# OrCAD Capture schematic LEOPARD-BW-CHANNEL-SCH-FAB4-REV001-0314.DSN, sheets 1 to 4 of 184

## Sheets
1 100_miniSAS CONNECTORS_SATA: size A2; title: MiniSAS CONNECTORS_SATA; rev: EVT; company: Wiwynn Corporation; note: LEOPARD BDW MAIN BOARD; note: 8F, 90, Sec.1, Xintai 5th Rd., Xizhi Dist.,; note: New Taipei, Taiwan
2 177_P3V3_STBY_TPS53318: size A3; title: P3V3_STBY_TPS53318; rev: PVT; note: 8F, No.90, Xintai 5th Rd., Xizhi Dist,
3 176_P3V3_TPS53319: size C; title: P3V3_TPS53319
4 175_P5V_STBY_TPS53319: size A3; title: P5V_STBY_TPS53319

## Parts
sheet 100_miniSAS CONNECTORS_SATA
C719  SCD01U16V2KX-3GP  [C402H22]
C723  SCD01U16V2KX-3GP  [C402H22]
C726  SCD01U16V2KX-3GP  [C402H22]
C728  SCD01U16V2KX-3GP  [C402H22]
C729  SCD01U16V2KX-3GP  [C402H22]
C730  SCD01U16V2KX-3GP  [C402H22]
C731  SCD01U16V2KX-3GP  [C402H22]
C733  SCD01U16V2KX-3GP  [C402H22]
C1019  SCD01U16V2KX-3GP  [C402H22]
C1020  SCD01U16V2KX-3GP  [C402H22]
C1021  SCD01U16V2KX-3GP  [C402H22]
C1022  SCD01U16V2KX-3GP  [C402H22]
C1023  SCD01U16V2KX-3GP  [C402H22]
C1024  SCD01U16V2KX-3GP  [C402H22]
C1025  SCD01U16V2KX-3GP  [C402H22]
C1026  SCD01U16V2KX-3GP  [C402H22]
C1027  SCD01U16V2KX-3GP  [C402H22]
C1028  SCD01U16V2KX-3GP  [C402H22]
C1029  SCD01U16V2KX-3GP  [C402H22]
C1030  SCD01U16V2KX-3GP  [C402H22]
C1031  SCD01U16V2KX-3GP  [C402H22]
C1032  SCD01U16V2KX-3GP  [C402H22]
C1033  SCD01U16V2KX-3GP  [C402H22]
C1034  SCD01U16V2KX-3GP  [C402H22]
C1035  SCD01U16V2KX-3GP  [C402H22]
C1036  SCD01U16V2KX-3GP  [C402H22]
C1037  SCD01U16V2KX-3GP  [C402H22]
C1038  SCD01U16V2KX-3GP  [C402H22]
C1039  SCD01U16V2KX-3GP  [C402H22]
C1040  SCD01U16V2KX-3GP  [C402H22]
C1041  SCD01U16V2KX-3GP  [C402H22]
C1042  SCD01U16V2KX-3GP  [C402H22]
MISAS1  AMP-CONN36-GP  [75784-0121]
MISAS2  AMP-CONN36-GP  [75784-0121]
R206  49D9R2F-GP  [R402H16]
R291  2KR2F-3-GP  [R402H16]
R293  2KR2F-3-GP  [R402H16]
R294  2KR2F-3-GP  [R402H16]
R295  2KR2F-3-GP  [R402H16]
R832  2KR2F-3-GP  [R402H16]
R835  2KR2F-3-GP  [R402H16]
R839  2KR2F-3-GP  [R402H16]
R840  2KR2F-3-GP  [R402H16]
R901  49D9R2F-GP  [R402H16]
R905  49D9R2F-GP  [R402H16]
R1262  49D9R2F-GP  [R402H16]
R1264  49D9R2F-GP  [R402H16]
R1265  49D9R2F-GP  [R402H16]
R1819  1KR2J-1-GP  [R402H16]
R1820  1KR2J-1-GP  [R402H16]
sheet 175_P5V_STBY_TPS53319
PC881  SC22U6D3V5MX-5-GP  [C805H56]
PC882  SC22U6D3V5MX-5-GP  [C805H56]
PC883  SC22U6D3V5MX-5-GP  [C805H56]
PC884  SC22U6D3V5MX-5-GP  [C805H56]
PC885  SC22U6D3V5MX-5-GP  [C805H56]
PC886  SC22U6D3V5MX-5-GP  [C805H56]
PC913  SCD1U16V2KX-3GP  [C402H22]
PC914  SC10U16V5KX-1-GP  [C805H54]
PC920  SC1U16V3KX-5GP  [C603H36]
PC921  SCD1U50V3KX-GP  [C603H36]
PC931  SC1KP50V2KX-1GP  [C402H22]
PC932  SCD1U16V3KX-3GP  [C603H36]
PC933  SC2K2P50V3KX-GP  [C603]
PC934  SC10U16V5KX-1-GP  [C805H54]
PC935  SCD1U50V3KX-GP  [C603H36]
PC936  SC22U6D3V5MX-5-GP  [C805H56]
PC937  SC10U16V5KX-1-GP  [C805H54]
PC938  SC10U16V5KX-1-GP  [C805H54]
PC939  SC10U16V5KX-1-GP  [C805H54]
PC940  SC4D7U25V5KX-1-GP  [C805H58]
PC1064  SC1U10V2KX-4-GP  [C402H22]
PD12  PTZ5D6B-GP  [D502715AKH87]
PG67  COPPER-CLOSE-GP-U  [CON2C-U]
PG68  GAP-CLOSE-PWR-4-GP  [GAP-CLOSE-PWR-4]
PL51  COIL-1UH-50-GP  [L7467-1432-1H119]
PL52  BLM21PG220SN1DGP  [L20125H42]
PR520  10KR2F-2-GP  [R402H16]
PR521  15KR2F-GP  [R402H16]
PR522  10KR2F-2-GP  [R402H16]
PR545  0R2J-2-GP  [R402H16]
PR628  2D7R3-GP  [R603H22]
PR631  2D2R3-1-U-GP  [R603H22]
PR634  10R3F-GP  [R603H22]
PR636  124KR2F-GP  [R402H16]
PR639  619KR2F-GP  [R402H16]
PR641  866KR2F-GP  [R402H16]
PR647  3D01R5F-GP  [R805H24]
PR648  1KR3F-GP  [R603H22]
PR650  71K5R3F-1-GP  [R603H22]
PR651  200KR2F-L-GP  [R402H16]
PR652  100KR2F-L1-GP  [R402H16]
PR653  10KR2F-2-GP  [R402H16]
PR816  0R2J-2-GP  [R402H16]
PR1910  2K2R2F-GP  [R402H16]
PU52  TPS53319DQPR-GP  [QFN22G6050-G6133H60]
sheet 176_P3V3_TPS53319
PC485  SC470P50V2KX-3GP  [C402H22]
PC790  SC22U6D3V5MX-5-GP  [C805H56]
PC792  SC22U6D3V5MX-5-GP  [C805H56]
PC793  SC22U6D3V5MX-5-GP  [C805H56]
PC794  SC22U6D3V5MX-5-GP  [C805H56]
PC795  SC22U6D3V5MX-5-GP  [C805H56]
PC836  SC22U6D3V5MX-5-GP  [C805H56]
PC904  SC10U16V5KX-1-GP  [C805H54]
PC905  SC10U16V5KX-1-GP  [C805H54]
PC906  SC10U16V5KX-1-GP  [C805H54]
PC907  SCD1U16V2KX-3GP  [C402H22]
PC908  SCD1U16V3KX-3GP  [C603H36]
PC909  SC22U6D3V5MX-5-GP  [C805H56]
PC911  SC10U16V5KX-1-GP  [C805H54]
PC917  SCD1U50V3KX-GP  [C603H36]
PC918  SC2K2P50V3KX-GP  [C603]
PC919  SCD1U50V3KX-GP  [C603H36]
PC941  SC4D7U25V5KX-1-GP  [C805H58]
PC942  SC1U16V3KX-5GP  [C603H36]
PC1055  SC1U10V2KX-4-GP  [C402H22]
PD11  PTZ5D6B-GP  [D502715AKH87]
PG64  COPPER-CLOSE-GP-U  [CON2C-U]
PL49  IND-1UH-188-GP  [L7166-1830-UH197]
PL50  BLM21PG220SN1DGP  [L20125H42]
PR2  147KR2F-L-GP  [R402H16]
PR3  309KR2F-GP  [R402H16]
PR4  309KR2F-GP  [R402H16]
PR347  20KR2F-L-GP  [R402H16]
PR441  10KR2F-2-GP  [R402H16]
PR481  2D7R3-GP  [R603H22]
PR540  10KR2F-2-GP  [R402H16]
PR541  10KR2F-2-GP  [R402H16]
PR543  0R2J-2-GP  [R402H16]
PR633  10R3F-GP  [R603H22]
PR635  44K2R2F-1-GP  [R402H16]
PR638  10KR2F-2-GP  [R402H16]
PR640  2KR2F-3-GP  [R402H16]
PR642  3D01R5F-GP  [R805H24]
PR649  2D2R3-1-U-GP  [R603H22]
PR817  0R2J-2-GP  [R402H16]
PR2171  39K2R2F-L-GP  [R402H16]
PR2172  39K2R2F-L-GP  [R402H16]
PU54  TPS53319DQPR-GP  [QFN22G6050-G6133H60]
sheet 177_P3V3_STBY_TPS53318
PC376  SC470P50V2KX-3GP  [C402H22]
PC386  SC1U10V2KX-4-GP  [C402H22]
PC392  SCD1U25V3KX-GP  [C603H36]
PC395  SCD1U50V3KX-GP  [C603H36]
PC488  SC2K2P50V3KX-GP  [C603]
PC489  SC4D7U25V5KX-1-GP  [C805H58]
PC808  SC22U6D3V5MX-5-GP  [C805H56]
PC835  SC10U16V5KX-1-GP  [C805H54]
PC851  SC10U16V5KX-1-GP  [C805H54]
PC852  SC10U16V5KX-1-GP  [C805H54]
PC1036  SC1U10V2KX-4-GP  [C402H22]
PG81  COPPER-CLOSE-GP-U  [CON2C-U]
PL19  BLM21PG220SN1DGP  [L20125H42]
PL42  IND-2D2UH-179-GP  [L7066-1830-UH119]
PR199  10R3F-GP  [R603H22]
PR200  0R5J-2  [R805H24]
PR201  2KR2F-3-GP  [R402H16]
PR202  100KR2F-L1-GP  [R402H16]
PR203  10KR2F-2-GP  [R402H16]
PR204  100KR2F-L1-GP  [R402H16]
PR207  475KR2F-GP  [R402H16]
PR209  3D01R5F-GP  [R805H24]
PR210  44K2R2F-1-GP  [R402H16]
PR211  0R2J-2-GP  [R402H16]
PR213  309KR2F-GP  [R402H16]
PR214  2D2R3-1-U-GP  [R603H22]
PR654  10KR2F-2-GP  [R402H16]
PTC19  ST150U6D3VBM-6-GP  [CT3528H83]
PU44  TPS53318DQPR-GP  [DFN22G6050-G6133H60]

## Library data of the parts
C719 C723 C726 C728-C731 C733 C1019-C1042 = SCD01U16V2KX-3GP: CHIP CAP0.01U16V K0402 X7R(ROH; Belong: POP; Category: PCH SAS; POP?: NOPOP; Part Number: 78.10321.2FL; Part Type: SMD-BCG
MISAS1 MISAS2 = AMP-CONN36-GP: CONN CTR SMD 36P G40MV36U11AEU ,LCP; GREENDFACTOR: R2_SA;; POP?: NOPOP; Part Number: 20.F1014.036; Part Type: CONN-G1; SPEC: http://wpqssvr.wistron.com.tw:7001/wpqs/servlet/COM.qpart.Attachment?PartNumber=20.F1014.036
R206 R901 R905 R1262 R1264 R1265 = 49D9R2F-GP: CHIP RES 49.9 F 1/16W 0402; GREENDFACTOR: R2_SA;HF_SA;G_SA;; POP?: NOPOP; Part Number: 64.49R95.6DL; Part Type: RCL_GP; SPEC: http://wpqssvr.wistron.com.tw:7001/wpqs/servlet/COM.qpart.Attachment?PartNumber=64.49R95.6DL
PR201 R291 R293-R295 R832 R835 R839 R840 = 2KR2F-3-GP: CHIP RES 2K F 1/16W 0402; Category: internal conn; DESCRIPTIO: CHIP RES 2K F 1/16W 0402; GREENDFACTOR: R2_SA;HF_SA;G_SA;; Package Type: SMD-RG; Part Number: 64.20015.6DL; Part Type: SMD-RG; SPEC: http://wpqssvr.wistron.com.tw:7001/wpqs/servlet/COM.qpart.Attachment?PartNumber=64.20015.6DL; VENDORPARTNUMBER: RM04FTN2001 / RTT022001FTH / RR0510S-202-FN / RC0402FR-072KL/WR04X2001FTL
R1819 R1820 = 1KR2J-1-GP: CHIP RES 1K J 1/16W 0402; GREENDFACTOR: R2_SA;HF_SA;G_SA;; POP?: NOPOP; Part Number: 63.10234.1DL; Part Type: SMD-RG; SPEC: http://wpqssvr.wistron.com.tw:7001/wpqs/servlet/COM.qpart.Attachment?PartNumber=63.10234.1DL
PC790 PC792-PC795 PC808 PC836 PC881-PC886 PC909 PC936 = SC22U6D3V5MX-5-GP: CHIP CAP C 22U 6.3V M0805 X6S; GREENDFACTOR: R2_SA;HF_SA;G_SA;; Package Type: SMD-BCG2; Part Number: 78.22610.81L; SPEC: http://wpqssvr.wistron.com.tw:7001/wpqs/servlet/COM.qpart.Attachment?PartNumber=78.22610.81L
PC907 PC913 = SCD1U16V2KX-3GP: CHIP CAP C 0.1U 16V K0402 X7R; GREENDFACTOR: R2_SA;HF_SA;G_SA;; MAIN_SOURCE: M; Package Type: SMD-BCG; Part Number: 78.10421.2FL; SPEC: http://wpqssvr.wistron.com.tw:7001/wpqs/servlet/COM.qpart.Attachment?PartNumber=78.10421.2FL
PC835 PC851 PC852 PC904-PC906 PC911 PC914 PC934 PC937-PC939 = SC10U16V5KX-1-GP: CHIP CAP C 10U 16V K0805 X6S; GREENDFACTOR: R2_SA;; Package Type: SMD-BCG5; Part Number: 78.10621.81L; SPEC: http://wpqssvr.wistron.com.tw:7001/wpqs/servlet/COM.qpart.Attachment?PartNumber=78.10621.81L
PC920 PC942 = SC1U16V3KX-5GP: CHIP CAP C 1U 16V K0603 X7R; GREENDFACTOR: R2_SA;HF_SA;G_SA;; Level: SMD; MAIN_SOURCE: M; Package Type: SMD-BCG3; Part Number: 78.10521.2BL; SPEC: http://wpqssvr.wistron.com.tw:7001/wpqs/servlet/COM.qpart.Attachment?PartNumber=78.10521.2BL; Status: POP
PC395 PC917 PC919 PC921 PC935 = SCD1U50V3KX-GP: CHIP CAP C 0.1U 50V K0603 X7R; GREENDFACTOR: R2_SA;HF_SA;G_SA;; Level: SMD; MAIN_SOURCE: M; Package Type: RCL_GP; Part Number: 78.10424.2BL; Part Type: RCL_GP; SPEC: http://wpqssvr.wistron.com.tw:7001/wpqs/servlet/COM.qpart.Attachment?PartNumber=78.10424.2BL; Status: POP
PC931 = SC1KP50V2KX-1GP: CHIP CAP 1000P50V K0402 X7R(RO; GREENDFACTOR: R2_SA;HF_SA;G_SA;; Level: SMD; MAIN_SOURCE: M; Package Type: SMD-BCG; Part Number: 78.10224.2FL; Part Type: SMD-BCG; SPEC: http://wpqssvr.wistron.com.tw:7001/wpqs/servlet/COM.qpart.Attachment?PartNumber=78.10224.2FL; Status: POP
PC908 PC932 = SCD1U16V3KX-3GP: CHIP CAP 0.1U16V K0603 X7R(ROH; GREENDFACTOR: R2_SA;R_SA;HF_SA;G_SA;; Module: VR_SYSTEM_P1V8; Package Type: SMD-BCG; Part Number: 78.10421.2BL; SPEC: http://wpqssvr.wistron.com.tw:7001/wpqs/servlet/COM.qpart.Attachment?PartNumber=78.10421.2BL; Size: 0603; Type: X7R
PC918 PC933 = SC2K2P50V3KX-GP: CHIP CAP C 2200P 50V K0603 X7R; GREENDFACTOR: R2_SA;HF_SA;G_SA;; Level: SMD; POP?: NOPOP; Package Type: SMD-BCG6; Part Number: 78.22224.2BL; Part Type: SMD-BCG6; SPEC: http://wpqssvr.wistron.com.tw:7001/wpqs/servlet/COM.qpart.Attachment?PartNumber=78.22224.2BL
PC489 PC940 PC941 = SC4D7U25V5KX-1-GP: CHIP CAP C 4.7U 25V K0805 X7R; GREENDFACTOR: R2_SA;HF_SA;G_SA;; Package Type: SMD-BCG4; Part Number: 078.47522.0211; SPEC: http://wpqssvr.wistron.com.tw:7001/wpqs/servlet/COM.qpart.Attachment?PartNumber=078.47522.0211
PC386 PC1064 = SC1U10V2KX-4-GP: CHIP CAP C 1U 10V K 0402 X6S; GREENDFACTOR: R2_SA;HF_SA;; Package Type: SMD-BCG6; Part Number: 78.10523.8FL; SPEC: http://wpqssvr.wistron.com.tw:7001/wpqs/servlet/COM.qpart.Attachment?PartNumber=78.10523.8FL
PD11 PD12 = PTZ5D6B-GP: DIODE ZEN PTZ5.6B 5.6V PMDS; GREENDFACTOR: R2_SA;; Package Type: DISCRET-G5; Part Number: 83.5R603.H3H; SPEC: http://wpqssvr.wistron.com.tw:7001/wpqs/servlet/COM.qpart.Attachment?PartNumber=83.5R603.H3H
PG64 PG67 PG81 = COPPER-CLOSE-GP-U: COPPER CLOSE; GREENDFACTOR: Regular;; Level: SMD; Package Type: DISCRET-G9; Part Number: ZZ.CON2C.XXX; Part Type: DISCRET-G9; SPEC: http://wpqssvr.wistron.com.tw:7001/wpqs/servlet/COM.qpart.Attachment?PartNumber=ZZ.CON2C.XXX
PG68 = GAP-CLOSE-PWR-4-GP: PAD FOR COPPER-CLOSE; GREENDFACTOR: R2_C;; Package Type: DISCRET-G7; Part Number: ZZ.C0N2C.011; SPEC: http://wpqssvr.wistron.com.tw:7001/wpqs/servlet/COM.qpart.Attachment?PartNumber=ZZ.C0N2C.011
PL51 = COIL-1UH-50-GP: CHIP CHOKE 1.0UH MPLCG0630L1R0; GREENDFACTOR: R2_SA;HF_SA;; Package Type: DISCRET-G4; Part Number: 68.1R010.20C; SPEC: http://wpqssvr.wistron.com.tw:7001/wpqs/servlet/COM.qpart.Attachment?PartNumber=68.1R010.20C
PL50 PL52 = BLM21PG220SN1DGP: CHIP BEAD BLM21PG220SN1D (LF); GREENDFACTOR: R2_SA;HF_SA;; Level: SMD; Package Type: DISCRET-G; Part Number: 68.00084.831; Part Type: DISCRET-G; SPEC: http://wpqssvr.wistron.com.tw:7001/wpqs/servlet/COM.qpart.Attachment?PartNumber=68.00084.831
PR520 PR522 = 10KR2F-2-GP: CHIP RES 10K F 1/16W 0402; GREENDFACTOR: R2_SA;HF_SA;G_SA;; Level: SMD; Package Type: SMD-RG; Part Number: 64.10025.6DL; SPEC: http://wpqssvr.wistron.com.tw:7001/wpqs/servlet/COM.qpart.Attachment?PartNumber=64.10025.6DL; Status: POP
PR521 = 15KR2F-GP: CHIP RES 15K F 1/16W 0402; GREENDFACTOR: R2_SA;HF_SA;G_SA;; Package Type: RCL_GP; Part Number: 64.15025.6DL; SPEC: http://wpqssvr.wistron.com.tw:7001/wpqs/servlet/COM.qpart.Attachment?PartNumber=64.15025.6DL
PR545 = 0R2J-2-GP: CHIP RES 0 J 1/16W 0402; Belong: POP; Category: Reset/PWRGD Logic; GREENDFACTOR: R2_SA;HF_SA;G_SA;; POP?: NOPOP; Part Number: 63.R0034.1DL; Part Type: SMD-RG; SPEC: http://wpqssvr.wistron.com.tw:7001/wpqs/servlet/COM.qpart.Attachment?PartNumber=63.R0034.1DL
PR481 PR628 = 2D7R3-GP: CHIP RES 2.7 J 1/10W 0603; GREENDFACTOR: R2_SA;HF_SA;G_SA;; Package Type: RCL_GP; Part Number: 63.2R734.15L; SPEC: http://wpqssvr.wistron.com.tw:7001/wpqs/servlet/COM.qpart.Attachment?PartNumber=63.2R734.15L
PR214 PR631 PR649 = 2D2R3-1-U-GP: CHIP RES 2.2 F 1/10W 0603(ROHS; GREENDFACTOR: R2_SA;HF_SA;G_SA;; Package Type: RCL_GP; Part Number: 64.2R205.55L; SPEC: http://wpqssvr.wistron.com.tw:7001/wpqs/servlet/COM.qpart.Attachment?PartNumber=64.2R205.55L
PR199 PR633 PR634 = 10R3F-GP: CHIP RES 10 F 1/10W 0603; GREENDFACTOR: R2_SA;HF_SA;G_SA;; Level: SMD; Package Type: RCL_GP; Part Number: 64.10R05.55L; Part Type: RCL_GP; SPEC: http://wpqssvr.wistron.com.tw:7001/wpqs/servlet/COM.qpart.Attachment?PartNumber=64.10R05.55L; Status: POP
PR636 = 124KR2F-GP: CHIP RES 124K F 1/16W 0402; GREENDFACTOR: R2_SA;HF_SA;G_SA;; Package Type: RCL_GP; Part Number: 64.12435.6DL; SPEC: http://wpqssvr.wistron.com.tw:7001/wpqs/servlet/COM.qpart.Attachment?PartNumber=64.12435.6DL
PR639 = 619KR2F-GP: CHIP RES 619K F 1/16W 0402; GREENDFACTOR: R2_SA;HF_SA;G_SA;; Level: SMD; POP?: NOPOP; Package Type: SMD-RG3; Part Number: 64.61935.6DL; Part Type: SMD-RG3; SPEC: http://wpqssvr.wistron.com.tw:7001/wpqs/servlet/COM.qpart.Attachment?PartNumber=64.61935.6DL
PR641 = 866KR2F-GP: CHP RES 866K F 1/16W 0402; GREENDFACTOR: R2_SA;HF_SA;G_SA;; Level: SMD; Package Type: SMD-RG4; Part Number: 64.86635.6DL; Part Type: SMD-RG4; SPEC: http://wpqssvr.wistron.com.tw:7001/wpqs/servlet/COM.qpart.Attachment?PartNumber=64.86635.6DL; Status: POP
PR642 PR647 = 3D01R5F-GP: CHIP RES 3.01 F 1/8W 0805; GREENDFACTOR: R2_SA;HF_SA;G_SA;; Level: SMD; POP?: NOPOP; Package Type: SMD-RG5; Part Number: 64.3R015.16L; Part Type: SMD-RG5; SPEC: http://wpqssvr.wistron.com.tw:7001/wpqs/servlet/COM.qpart.Attachment?PartNumber=64.3R015.16L
PR648 = 1KR3F-GP: CHIP RES 1K F 1/10W 0603(ROHS); GREENDFACTOR: R2_SA;HF_SA;G_SA;; Part Number: 64.10015.55L; Part Type: RCL_GP; SPEC: http://wpqssvr.wistron.com.tw:7001/wpqs/servlet/COM.qpart.Attachment?PartNumber=64.10015.55L
PR650 = 71K5R3F-1-GP: CHIP RES 71.5K F 1/10W 0603; GREENDFACTOR: R2_SA;HF_SA;G_SA;; Part Number: 64.71525.55L; Part Type: SMD-RG; SPEC: http://wpqssvr.wistron.com.tw:7001/wpqs/servlet/COM.qpart.Attachment?PartNumber=64.71525.55L
PR651 = 200KR2F-L-GP: CHIP RES 200K F 1/16W 0402; GREENDFACTOR: R2_SA;HF_SA;G_SA;; Package Type: SMD-RG; Part Number: 64.20035.6DL; SPEC: http://wpqssvr.wistron.com.tw:7001/wpqs/servlet/COM.qpart.Attachment?PartNumber=64.20035.6DL
PR652 = 100KR2F-L1-GP: CHIP RES 100K F 1/16W 0402; GREENDFACTOR: R2_SA;HF_SA;G_SA;; Level: SMD; POP?: NOPOP; Package Type: SMD-RG; Part Number: 64.10035.6DL; Part Type: SMD-RG; SPEC: http://wpqssvr.wistron.com.tw:7001/wpqs/servlet/COM.qpart.Attachment?PartNumber=64.10035.6DL
PR441 PR541 PR638 PR653 PR654 = 10KR2F-2-GP: CHIP RES 10K F 1/16W 0402; GREENDFACTOR: R2_SA;HF_SA;G_SA;; Level: SMD; Package Type: SMD-RG; Part Number: 64.10025.6DL; Part Type: SMD-RG; SPEC: http://wpqssvr.wistron.com.tw:7001/wpqs/servlet/COM.qpart.Attachment?PartNumber=64.10025.6DL
PR211 PR816 PR817 = 0R2J-2-GP: CHIP RES 0 J 1/16W 0402; GREENDFACTOR: R2_SA;HF_SA;G_SA;; Level: SMD; Package Type: SMD-RG; Part Number: 63.R0034.1DL; Part Type: SMD-RG; ROOM: VR_CHIPSET; SPEC: http://wpqssvr.wistron.com.tw:7001/wpqs/servlet/COM.qpart.Attachment?PartNumber=63.R0034.1DL; Status: POP
PR1910 = 2K2R2F-GP: CHIP RES 2.2K F 1/16W 0402; GREENDFACTOR: R2_SA;HF_SA;G_SA;; Package Type: RCL_GP; Part Number: 64.22015.6DL; SPEC: http://wpqssvr.wistron.com.tw:7001/wpqs/servlet/COM.qpart.Attachment?PartNumber=64.22015.6DL
PU52 PU54 = TPS53319DQPR-GP: IC PWR CTRL TPS53319DQPR QFN 22P; GREENDFACTOR: R2_SA;HF_SA;; Part Number: 74.53319.073; Part Type: DISCRET-G8; SPEC: http://wpqssvr.wistron.com.tw:7001/wpqs/servlet/COM.qpart.Attachment?PartNumber=74.53319.073
PC376 PC485 = SC470P50V2KX-3GP: CHIP CAP 470P50V K0402 X7R(ROH; CATEGORIES: CAP_Small; GREENDFACTOR: R2_SA;HF_SA;G_SA;; MAIN_SOURCE: M; Package Type: SMD-BCG; Part Number: 78.47124.2FL; SPEC: http://wpqssvr.wistron.com.tw:7001/wpqs/servlet/COM.qpart.Attachment?PartNumber=78.47124.2FL
PC1036 PC1055 = SC1U10V2KX-4-GP: CHIP CAP C 1U 10V K 0402 X6S; GREENDFACTOR: R2_SA;HF_SA;; POP?: NOPOP; Package Type: SMD-BCG6; Part Number: 78.10523.8FL; SPEC: http://wpqssvr.wistron.com.tw:7001/wpqs/servlet/COM.qpart.Attachment?PartNumber=78.10523.8FL
PL49 = IND-1UH-188-GP: CHIP IND 1UH M PCMB065T-1R0MS; GREENDFACTOR: R2_SA;; Package Type: DISCRET-G7; Part Number: 68.1R01E.10D; SPEC: http://wpqssvr.wistron.com.tw:7001/wpqs/servlet/COM.qpart.Attachment?PartNumber=68.1R01E.10D
PR2 = 147KR2F-L-GP: CHIP RES 147K F 1/16W 0402; GREENDFACTOR: R2_SA;HF_SA;G_SA;; Part Number: 64.14735.L1L; Part Type: SMD-RG5; SPEC: http://wpqssvr.wistron.com.tw:7001/wpqs/servlet/COM.qpart.Attachment?PartNumber=64.14735.L1L
PR3 = 309KR2F-GP: CHIP RES 309K F 1/16W 0402; GREENDFACTOR: R2_SA;HF_SA;G_SA;; Package Type: SMD-RG; Part Number: 64.30935.6DL; SPEC: http://wpqssvr.wistron.com.tw:7001/wpqs/servlet/COM.qpart.Attachment?PartNumber=64.30935.6DL
PR4 = 309KR2F-GP: CHIP RES 309K F 1/16W 0402; GREENDFACTOR: R2_SA;HF_SA;G_SA;; POP?: NOPOP; Package Type: SMD-RG; Part Number: 64.30935.6DL; SPEC: http://wpqssvr.wistron.com.tw:7001/wpqs/servlet/COM.qpart.Attachment?PartNumber=64.30935.6DL
PR347 = 20KR2F-L-GP: CHIP RES 20K F 1/16W 0402; GREENDFACTOR: R2_SA;HF_SA;G_SA;; Part Number: 64.20025.6DL; Part Type: SMD-RG; SPEC: http://wpqssvr.wistron.com.tw:7001/wpqs/servlet/COM.qpart.Attachment?PartNumber=64.20025.6DL
PR540 = 10KR2F-2-GP: CHIP RES 10K F 1/16W 0402; GREENDFACTOR: R2_SA;HF_SA;G_SA;; Level: SMD; POP?: NOPOP; Package Type: SMD-RG; Part Number: 64.10025.6DL; Part Type: SMD-RG; SPEC: http://wpqssvr.wistron.com.tw:7001/wpqs/servlet/COM.qpart.Attachment?PartNumber=64.10025.6DL
PR543 = 0R2J-2-GP: CHIP RES 0 J 1/16W 0402; GREENDFACTOR: R2_SA;HF_SA;G_SA;; Level: SMD; Package Type: SMD-RG; Part Number: 63.R0034.1DL; ROOM: VR_CHIPSET; SPEC: http://wpqssvr.wistron.com.tw:7001/wpqs/servlet/COM.qpart.Attachment?PartNumber=63.R0034.1DL; Status: POP
PR635 = 44K2R2F-1-GP: CHIP RES 44.2K F 1/16W 0402; GREENDFACTOR: R2_SA;HF_SA;G_SA;; Part Number: 64.44225.6DL; Part Type: SMD-RG; SPEC: http://wpqssvr.wistron.com.tw:7001/wpqs/servlet/COM.qpart.Attachment?PartNumber=64.44225.6DL
PR640 = 2KR2F-3-GP: CHIP RES 2K F 1/16W 0402; GREENDFACTOR: R2_SA;HF_SA;G_SA;; Package Type: SMD-RG; Part Number: 64.20015.6DL; SPEC: http://wpqssvr.wistron.com.tw:7001/wpqs/servlet/COM.qpart.Attachment?PartNumber=64.20015.6DL
PR2171 = 39K2R2F-L-GP: CHIP RES 39.2K F 1/16W 0402; GREENDFACTOR: R2_SA;HF_SA;G_SA;; POP?: NOPOP; Package Type: SMD-RG; Part Number: 64.39225.6DL; SPEC: http://wpqssvr.wistron.com.tw:7001/wpqs/servlet/COM.qpart.Attachment?PartNumber=64.39225.6DL
PR2172 = 39K2R2F-L-GP: CHIP RES 39.2K F 1/16W 0402; GREENDFACTOR: R2_SA;HF_SA;G_SA;; Package Type: SMD-RG; Part Number: 64.39225.6DL; SPEC: http://wpqssvr.wistron.com.tw:7001/wpqs/servlet/COM.qpart.Attachment?PartNumber=64.39225.6DL
PC392 = SCD1U25V3KX-GP: CHIP CAP C 0.1U 25V K0603 X7R; CATEGORIES: CAP_1.xV; GREENDFACTOR: R2_SA;HF_SA;G_SA;; MAIN_SOURCE: M; Package Type: RCL_GP; Part Number: 78.10422.2BL; SPEC: http://wpqssvr.wistron.com.tw:7001/wpqs/servlet/COM.qpart.Attachment?PartNumber=78.10422.2BL
PC488 = SC2K2P50V3KX-GP: CHIP CAP C 2200P 50V K0603 X7R; GREENDFACTOR: R2_SA;HF_SA;G_SA;; Level: SMD; POP?: NOPOP; Package Type: SMD-BCG6; Part Number: 78.22224.2BL; Part Type: SMD-BCG6; SPEC: http://wpqssvr.wistron.com.tw:7001/wpqs/servlet/COM.qpart.Attachment?PartNumber=78.22224.2BL; Status: POP
PL19 = BLM21PG220SN1DGP: CHIP BEAD BLM21PG220SN1D (LF); GREENDFACTOR: R2_SA;HF_SA;; Level: SMD; Package Type: DISCRET-G; Part Number: 68.00084.831; Part Type: DISCRET-G; SPEC: http://wpqssvr.wistron.com.tw:7001/wpqs/servlet/COM.qpart.Attachment?PartNumber=68.00084.831; Status: POP
PL42 = IND-2D2UH-179-GP: CHIP CHOKE 2.2U PCMB063T-2R2MS; Part Number: 68.2R21A.20B; Part Type: DISCRET-G8; SPEC: http://wpqssvr.wistron.com.tw:7001/wpqs/servlet/COM.qpart.Attachment?PartNumber=68.2R21A.20B
PR200 = 0R2: CHIP RES 0 J 1/8W 0805 SMD; POP?: BOM use 63.R0031.16L; Part Number: 63.R0031.161; Part Type: SMD-R; SPEC: http://wpqssvr.wistron.com.tw:7001/wpqs/servlet/COM.qpart.Attachment?PartNumber=63.R0031.161
PR202 = 100KR2F-L1-GP: CHIP RES 100K F 1/16W 0402; GREENDFACTOR: R2_SA;HF_SA;G_SA;; Level: SMD; Package Type: SMD-RG; Part Number: 64.10035.6DL; Part Type: SMD-RG; SPEC: http://wpqssvr.wistron.com.tw:7001/wpqs/servlet/COM.qpart.Attachment?PartNumber=64.10035.6DL; Status: NOPOP
PR203 = 10KR2F-2-GP: CHIP RES 10K F 1/16W 0402; GREENDFACTOR: R2_SA;HF_SA;G_SA;; Package Type: SMD-RG; Part Number: 64.10025.6DL; SPEC: http://wpqssvr.wistron.com.tw:7001/wpqs/servlet/COM.qpart.Attachment?PartNumber=64.10025.6DL
PR204 = 100KR2F-L1-GP: CHIP RES 100K F 1/16W 0402; GREENDFACTOR: R2_SA;HF_SA;G_SA;; Level: SMD; POP?: NOPOP; Package Type: SMD-RG; Part Number: 64.10035.6DL; Part Type: SMD-RG; SPEC: http://wpqssvr.wistron.com.tw:7001/wpqs/servlet/COM.qpart.Attachment?PartNumber=64.10035.6DL; Status: NOPOP
PR207 = 475KR2F-GP: CHIP RES 475K F 1/16W 0402; GREENDFACTOR: R2_SA;HF_SA;G_SA;; Level: SMD; Package Type: SMD-RG3; Part Number: 64.47535.6DL; Part Type: SMD-RG3; SPEC: http://wpqssvr.wistron.com.tw:7001/wpqs/servlet/COM.qpart.Attachment?PartNumber=64.47535.6DL
PR209 = 3D01R5F-GP: CHIP RES 3.01 F 1/8W 0805; GREENDFACTOR: R2_SA;HF_SA;G_SA;; Level: SMD; POP?: NOPOP; Package Type: SMD-RG5; Part Number: 64.3R015.16L; Part Type: SMD-RG5; SPEC: http://wpqssvr.wistron.com.tw:7001/wpqs/servlet/COM.qpart.Attachment?PartNumber=64.3R015.16L; Status: POP
PR210 = 44K2R2F-1-GP: CHIP RES 44.2K F 1/16W 0402; Part Number: 64.44225.6DL; Part Type: SMD-RG; SPEC: http://wpqssvr.wistron.com.tw:7001/wpqs/servlet/COM.qpart.Attachment?PartNumber=64.44225.6DL
PR213 = 309KR2F-GP: CHIP RES 309K F 1/16W 0402; GREENDFACTOR: R2_SA;HF_SA;G_SA;; Part Number: 64.30935.6DL; Part Type: SMD-RG; SPEC: http://wpqssvr.wistron.com.tw:7001/wpqs/servlet/COM.qpart.Attachment?PartNumber=64.30935.6DL
PTC19 = ST150U6D3VBM-6-GP: CHIP CAP T150U6.3V M3528 ESR25; GREENDFACTOR: R2_SA;; Part Number: 80.15715.A2L; Part Type: SMD-TCG2; SPEC: http://wpqssvr.wistron.com.tw:7001/wpqs/servlet/COM.qpart.Attachment?PartNumber=80.15715.A2L
PU44 = TPS53318DQPR-GP: IC PWR CTRL TPS53318DQPR QFN 22P; GREENDFACTOR: R2_C;HF_C;; Package Type: DISCRET-G5; Part Number: 74.53318.073; SPEC: http://wpqssvr.wistron.com.tw:7001/wpqs/servlet/COM.qpart.Attachment?PartNumber=74.53318.073

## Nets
AGND_P3V3: PG64.1 PR2.1 PR4.1 PR638.2 PR817.2 PR2171.1
AGND_P3V3_STBY: PG81.1 PR202.1 PR203.2 PR204.1
AGND_P5V: PG67.1 PR636.1 PR639.2 PR652.1 PR653.2 PR816.2
GND: MISAS1.A1(GND) MISAS1.A4(GND) MISAS1.A7(GND) MISAS1.A9(SB1) MISAS1.A12(GND) MISAS1.A15(GND) MISAS1.A18(GND) MISAS1.B1(GND) MISAS1.B4(GND) MISAS1.B7(GND) MISAS1.B10(SB4) MISAS1.B12(GND) MISAS1.B15(GND) MISAS1.B18(GND) MISAS1.MH1 MISAS1.MH2 MISAS1.MH3 MISAS1.MH4 MISAS1.MH5 MISAS1.MH6 MISAS1.MH7 MISAS1.MH8 MISAS2.A1(GND) MISAS2.A4(GND) MISAS2.A7(GND) MISAS2.A9(SB1) MISAS2.A12(GND) MISAS2.A15(GND) MISAS2.A18(GND) MISAS2.B1(GND) MISAS2.B4(GND) MISAS2.B7(GND) MISAS2.B10(SB4) MISAS2.B12(GND) MISAS2.B15(GND) MISAS2.B18(GND) MISAS2.MH1 MISAS2.MH2 MISAS2.MH3 MISAS2.MH4 MISAS2.MH5 MISAS2.MH6 MISAS2.MH7 MISAS2.MH8 PC386.2 PC489.2 PC790.2 PC792.2 PC793.2 PC794.2 PC795.2 PC808.2 PC835.2 PC836.2 PC851.2 PC852.2 PC881.2 PC882.2 PC883.2 PC884.2 PC885.2 PC886.2 PC904.2 PC905.2 PC906.2 PC907.2 PC908.2 PC909.2 PC911.2 PC913.2 PC914.2 PC920.1 PC932.2 PC934.2 PC936.2 PC937.2 PC938.2 PC939.2 PC940.2 PC941.2 PC942.1 PC1036.2 PC1055.1 PC1064.2 PD11.A(ANODE) PD12.A(ANODE) PG64.2 PG67.2 PG81.2 PR209.2 PR347.1 PR521.2 PR541.2 PR642.2 PR647.2 PR1910.2 PTC19.2 PU44.5(ROVP) PU44.23(GND) PU52.23(GND) PU54.23(GND) R1819.2 R1820.2 ; also on sheet 5 6 7 8 9 10 11 12 13 14 15 16 17 18 19 20 21 22 23 24 25 26 27 28 29 30 31 32 33 34 35 36 37 38 39 44 46 47 49 50 51 52 53 54 55 56 57 58 59 60 61 62 63 64 65 66 69 70 71 73 74 75 76 78 79 80 81 82 83 84 86 87 88 89 90 91 92 93 94 95 96 97 98 99 100 101 102 103 104 105 106 107 108 109 110 111 112 113 114 115 116 117 118 119 128 129 138 139 159 160 161 166 168 169 170 171 172 173 174 175 176 177 180 181 182 183 184
P3V3: PC790.1 PC792.1 PC793.1 PC794.1 PC795.1 PC836.1 PC908.1 PC909.1 PC919.1 PD11.K(CATHODE) PL49.2 PR633.1 R291.1 R293.1 R294.1 R295.1 R832.1 R835.1 R839.1 R840.1 ; also on sheet 8 45 46 48 49 52 54 58 65 74 76 78 83 84 87 90 91 94 95 96 100 101 102 161 166 168 173 174 177 180 181 182 183
P3V3_EN: PC1055.2 PR540.2 PR543.1 PU54.2(EN)
P3V3_LL: PC917.2 PC918.1 PL49.1 PR640.1 PU54.6(LL#6) PU54.7(LL#7) PU54.8(LL#8) PU54.9(LL#9) PU54.10(LL#10) PU54.11(LL#11)
P3V3_LL_R: PC485.1 PC919.2 PR640.2
P3V3_MODE: PR2171.2 PR2172.1 PU54.20(MODE)
P3V3_RF: PR3.2 PR4.2 PU54.22(RF)
P3V3_ROVP: PR817.1 PU54.5(ROVP)
P3V3_SNB: PC918.2 PR642.1
P3V3_STBY: PC392.2 PC808.1 PL42.2 PR199.1 PR540.1 PR654.1 PTC19.1 ; also on sheet 5 6 8 9 10 11 12 15 16 17 20 21 22 25 26 27 30 31 33 34 35 37 38 39 45 47 49 50 51 52 54 55 59 60 61 62 63 64 65 66 69 70 71 72 73 74 76 79 83 84 87 88 89 90 91 92 93 94 95 96 97 98 99 159 161 166 168 173 174 176 177 179 180 182 183 184
P3V3_STBY_EN: PC1036.1 PR211.2 PU44.2(EN)
P3V3_STBY_LL: PC395.2 PC488.1 PL42.1 PR201.1 PU44.6(LL#6) PU44.7(LL#7) PU44.8(LL#8) PU44.9(LL#9) PU44.10(LL#10) PU44.11(LL#11)
P3V3_STBY_LL_R: PC376.1 PC392.1 PR201.2
P3V3_STBY_MODE: PR204.2 PR207.1 PU44.20(MODE)
P3V3_STBY_RF: PR213.2 PU44.22(RF)
P3V3_STBY_SNB: PC488.2 PR209.1
P3V3_STBY_TRIP: PR202.2 PU44.21(TRIP)
P3V3_STBY_VBST: PR200.1 PU44.4(VBST)
P3V3_STBY_VBST_RC: PC395.1 PR200.2
P3V3_STBY_VDD: PC489.1 PR214.2 PU44.19(VDD)
P3V3_STBY_VFB: PC376.2 PR203.1 PR210.1 PU44.1(VFB)
P3V3_STBY_VFB_R: PR199.2 PR210.2
P3V3_STBY_VIN: PC835.1 PC851.1 PC852.1 PL19.2 PU44.12(VIN) PU44.13(VIN) PU44.14(VIN) PU44.15(VIN) PU44.16(VIN) PU44.17(VIN)
P3V3_STBY_VREG: PC386.1 PR213.1 PU44.18(VREG)
P3V3_TRIP: PR2.2 PU54.21(TRIP)
P3V3_VBST: PR481.1 PU54.4(VBST)
P3V3_VBST_RC: PC917.1 PR481.2
P3V3_VDD: PC941.1 PR649.2 PU54.19(VDD)
P3V3_VFB: PC485.2 PR635.1 PR638.1 PU54.1(VFB)
P3V3_VFB_R: PR633.2 PR635.2
P3V3_VIN: PC904.1 PC905.1 PC906.1 PC907.1 PC911.1 PL50.2 PU54.12(VIN) PU54.13(VIN) PU54.14(VIN) PU54.15(VIN) PU54.16(VIN) PU54.17(VIN)
P3V3_VREG: PC942.2 PR3.1 PR441.2 PU54.18(VREG)
P5V_CC: PG68.2 PR634.1
P5V_EN_R: PC1064.1 PR522.2 PR545.2 PR1910.1 PU52.2(EN)
P5V_LL: PC933.1 PC935.2 PL51.1 PR648.1 PU52.6(LL#6) PU52.7(LL#7) PU52.8(LL#8) PU52.9(LL#9) PU52.10(LL#10) PU52.11(LL#11)
P5V_LL_R: PC921.2 PC931.1 PR648.2
P5V_MODE: PR651.1 PR652.2 PU52.20(MODE)
P5V_RF: PR639.1 PR641.1 PU52.22(RF)
P5V_ROVP: PR816.1 PU52.5(ROVP)
P5V_SNB: PC933.2 PR647.1
P5V_STBY: PC881.1 PC882.1 PC883.1 PC884.1 PC885.1 PC886.1 PC921.1 PC932.1 PC936.1 PD12.K(CATHODE) PG68.1 PL51.2 PR520.1 ; also on sheet 5 6 8 14 15 19 20 24 25 29 30 33 34 37 38 59 61 65 69 76 95
P5V_TRIP: PR636.2 PU52.21(TRIP)
P5V_VBST: PR628.1 PU52.4(VBST)
P5V_VBST_RC: PC935.1 PR628.2
P5V_VDD: PC940.1 PR631.2 PU52.19(VDD)
P5V_VFB: PC931.2 PR650.1 PR653.1 PU52.1(VFB)
P5V_VFB_R: PR634.2 PR650.2
P5V_VIN: PC913.1 PC914.1 PC934.1 PC937.1 PC938.1 PC939.1 PL52.2 PU52.12(VIN) PU52.13(VIN) PU52.14(VIN) PU52.15(VIN) PU52.16(VIN) PU52.17(VIN)
P5V_VREG: PC920.2 PR641.2 PU52.18(VREG)
P12V_STBY: PL19.1 PL50.1 PL52.1 PR214.1 PR522.1 PR631.1 PR649.1 ; also on sheet 7 9 10 11 12 13 17 18 22 23 27 28 32 36 59 60 75 95 104 105 106 107 108 109 110 111 112 113 114 115 116 117 118 119
FM_P3V3_CPLD_EN: PR541.1 PR543.2 ; also on sheet 51
MB0_P12V_PWRGOOD: PR545.1 ; also on sheet 60
PD_SAS0_B11: MISAS2.B11(SB5) R1819.1
PD_SAS1_B11: MISAS1.B11(SB5) R1820.1
PU_DATAIN1_SAS0: MISAS2.A11(SB6) R839.2
PU_DATAIN1_SAS1: MISAS1.A11(SB6) R840.2
PWRGD_P3V3: PR347.2 PR441.1 PR2172.2 PU54.3(PGOOD) ; also on sheet 8 51
PWRGD_P3V3_AUX: PR207.2 PR654.2 PU44.3(PGOOD) ; also on sheet 7 55
PWRGD_P5V_STBY: PR211.1 PR520.2 PR521.1 PR651.2 PU52.3(PGOOD)
SATA0_TX_C_DN: C731.2 ; also on sheet 91
SATA0_TX_C_DP: C733.2 ; also on sheet 91
SATA0_TX_CC_DN: C731.1 MISAS1.B3(TX0_N)
SATA0_TX_CC_DP: C733.1 MISAS1.B2(TX0)
SATA1_TX_C_DN: C1035.2 ; also on sheet 91
SATA1_TX_C_DP: C1039.2 ; also on sheet 91
SATA1_TX_CC_DN: C1035.1 MISAS1.B6(TX1_N)
SATA1_TX_CC_DP: C1039.1 MISAS1.B5(TX1)
SATA2_TX_C_DN: C1033.2 ; also on sheet 91
SATA2_TX_C_DP: C1038.2 ; also on sheet 91
SATA2_TX_CC_DN: C1033.1 MISAS1.B14(TX2_N)
SATA2_TX_CC_DP: C1038.1 MISAS1.B13(TX2)
SATA3_TX_C_DN: C1036.2 ; also on sheet 91
SATA3_TX_C_DP: C1032.2 ; also on sheet 91
SATA3_TX_CC_DN: C1036.1 MISAS1.B17(TX3_N)
SATA3_TX_CC_DP: C1032.1 MISAS1.B16(TX3)
SATA6G_P0_RX_C_DN: C729.1 MISAS1.A3(RX0_N)
SATA6G_P0_RX_C_DP: C730.1 MISAS1.A2(RX0)
SATA6G_P0_RX_DN: C729.2 ; also on sheet 91
SATA6G_P0_RX_DP: C730.2 ; also on sheet 91
SATA6G_P1_RX_C_DN: C1034.1 MISAS1.A6(RX1_N)
SATA6G_P1_RX_C_DP: C1031.1 MISAS1.A5(RX1)
SATA6G_P1_RX_DN: C1034.2 ; also on sheet 91
SATA6G_P1_RX_DP: C1031.2 ; also on sheet 91
SATA6G_P2_RX_C_DN: C1041.1 MISAS1.A14(RX2_N)
SATA6G_P2_RX_C_DP: C1040.1 MISAS1.A13(RX2)
SATA6G_P2_RX_DN: C1041.2 ; also on sheet 91
SATA6G_P2_RX_DP: C1040.2 ; also on sheet 91
SATA6G_P3_RX_C_DN: C1037.1 MISAS1.A17(RX3_N)
SATA6G_P3_RX_C_DP: C1042.1 MISAS1.A16(RX3)
SATA6G_P3_RX_DN: C1037.2 ; also on sheet 91
SATA6G_P3_RX_DP: C1042.2 ; also on sheet 91
SGPIO_SATA_CLOCK: R293.2 R1262.2 ; also on sheet 91
SGPIO_SATA_CLOCK_R1: MISAS1.B8(SB7) R1262.1
SGPIO_SATA_DATAOUT0: R835.2 R1265.1 ; also on sheet 91
SGPIO_SATA_DATAOUT0_R1: MISAS1.A10(SB2) R1265.2
SGPIO_SATA_LOAD: R832.2 R1264.2 ; also on sheet 91
SGPIO_SATA_LOAD_R1: MISAS1.B9(SB3) R1264.1
SGPIO_SSATA_CLOCK: R206.2 R291.2 ; also on sheet 91
SGPIO_SSATA_CLOCK_R1: MISAS2.B8(SB7) R206.1
SGPIO_SSATA_DATAOUT0: R295.2 R905.1 ; also on sheet 91
SGPIO_SSATA_DATAOUT0_R1: MISAS2.A10(SB2) R905.2
SGPIO_SSATA_LOAD: R294.2 R901.2 ; also on sheet 91
SGPIO_SSATA_LOAD_R1: MISAS2.B9(SB3) R901.1
SSATA6G_0_RX_C_DN: C719.2 ; also on sheet 91
SSATA6G_0_RX_C_DP: C723.2 ; also on sheet 91
SSATA6G_0_RX_CC_DN: C719.1 MISAS2.A3(RX0_N)
SSATA6G_0_RX_CC_DP: C723.1 MISAS2.A2(RX0)
SSATA6G_0_TX_C_DN: C726.2 ; also on sheet 91
SSATA6G_0_TX_C_DP: C728.2 ; also on sheet 91
SSATA6G_0_TX_CC_DN: C726.1 MISAS2.B3(TX0_N)
SSATA6G_0_TX_CC_DP: C728.1 MISAS2.B2(TX0)
SSATA6G_1_RX_C_DN: C1022.2 ; also on sheet 91
SSATA6G_1_RX_C_DP: C1020.2 ; also on sheet 91
SSATA6G_1_RX_CC_DN: C1022.1 MISAS2.A6(RX1_N)
SSATA6G_1_RX_CC_DP: C1020.1 MISAS2.A5(RX1)
SSATA6G_1_TX_C_DN: C1021.2 ; also on sheet 91
SSATA6G_1_TX_C_DP: C1019.2 ; also on sheet 91
SSATA6G_1_TX_CC_DN: C1021.1 MISAS2.B6(TX1_N)
SSATA6G_1_TX_CC_DP: C1019.1 MISAS2.B5(TX1)
SSATA6G_2_RX_C_DN: C1026.2 ; also on sheet 91
SSATA6G_2_RX_C_DP: C1024.2 ; also on sheet 91
SSATA6G_2_RX_CC_DN: C1026.1 MISAS2.A14(RX2_N)
SSATA6G_2_RX_CC_DP: C1024.1 MISAS2.A13(RX2)
SSATA6G_2_TX_C_DN: C1025.2 ; also on sheet 91
SSATA6G_2_TX_C_DP: C1023.2 ; also on sheet 91
SSATA6G_2_TX_CC_DN: C1025.1 MISAS2.B14(TX2_N)
SSATA6G_2_TX_CC_DP: C1023.1 MISAS2.B13(TX2)
SSATA6G_3_RX_C_DN: C1030.2 ; also on sheet 91
SSATA6G_3_RX_C_DP: C1028.2 ; also on sheet 91
SSATA6G_3_RX_CC_DN: C1030.1 MISAS2.A17(RX3_N)
SSATA6G_3_RX_CC_DP: C1028.1 MISAS2.A16(RX3)
SSATA6G_3_TX_C_DN: C1029.2 ; also on sheet 91
SSATA6G_3_TX_C_DP: C1027.2 ; also on sheet 91
SSATA6G_3_TX_CC_DN: C1029.1 MISAS2.B17(TX3_N)
SSATA6G_3_TX_CC_DP: C1027.1 MISAS2.B16(TX3)

Not connected (* = marked no-connect by the designer): MISAS1 A8(SB0)* NP1* NP2*; MISAS2 A8(SB0)* NP1* NP2*

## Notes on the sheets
sheet 1
- miniSAS CONNECTORS_SATA
- FAB2 REV001 20150701
- FAB2 REV001 20150701
sheet 2
- Power rail : P3V3_STBY
  Controller : TPS53318 (Fswitching=750KHz)
  TDC : 6.4A
  MAX :6.4A
  OCP :7.7A
- I_rated=6A
  DCR=20mohm
  Z=22ohm
- CYNTEC PCMB063T-2R2MS
  L=2.2uH, DCR=13.5 m ohm,
  IDA1=8, IDC2=10
  6.6*7.3*3.0mm
- FCCM Mode
- SS=5.6ms
- OCP =7.7A
- FS=750KHz
- Vout=0.6x(1+Ru/Rd)=3.252V
- FAB3 REV003 20151103
- ESR=25mohm
sheet 3
- Power rail : P3V3
  Controller : TPS53319 (Fswitching=750KHz)
  TDC : 10.4A
  MAX : 10.4A
  OCP : 13A
- vender P/N:PCMB065T-1R0MS
  DCR:5.6m ohm max:6.5m ohm
  Idc:13A  Isat:15A
  Dimensions:7.05 * 6.6 * 4.8 (mm)
- SS=1ms
- FCCM Mode
- OCP =13A
- FAB2 REV004 20150730
- FS=750KHz
sheet 4
- Power rail : P5V_STBY
  Controller : TPS53319 (Fswitching=600KHz)
  TDC :8.1A
  MAX : 8.1A
  OCP :12A
- Input-Cap RMS Current = 3.97A
- I_rated=6A
  DCR=20mohm
  Z=22ohm
- NEC IMPLCG0630
  L=1uH, DCR=8.4m ohm,
  Idc1=12A, Idc2=9A
  7.7*6.7*3 mm
- FCCM Mode
- SS=2.8ms
- FAB2 REV002 20150713
- Vout=0.6x(1+Ru/Rd)
  =5.0V
- OC=12.0A
- FAB3 REV001 20151014
- FS=600KHz
